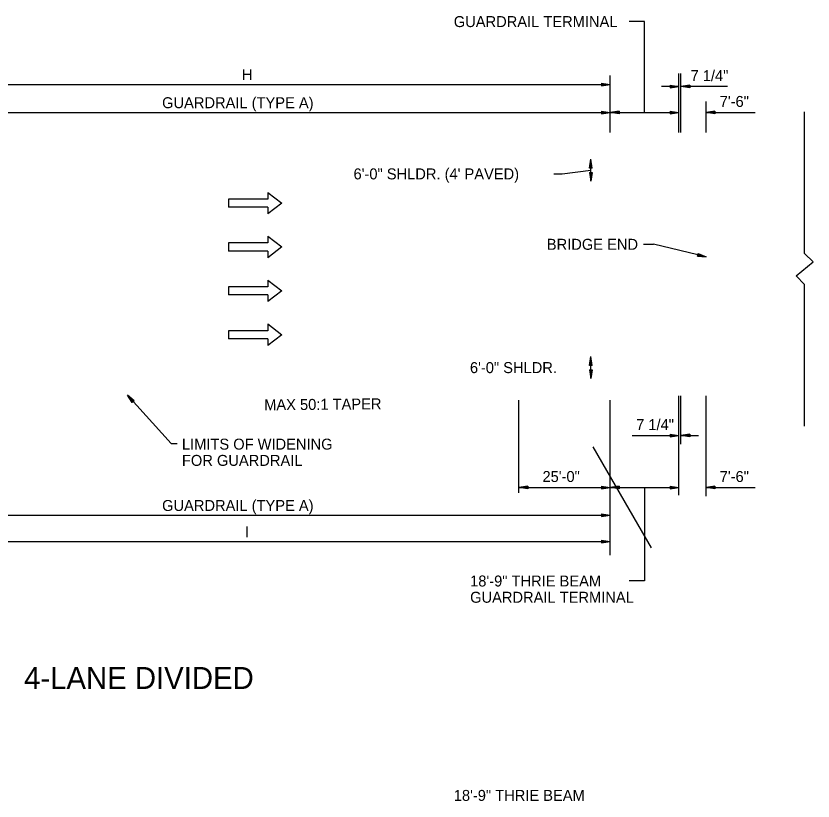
# Model space of a CAD drawing. Extents: x 1373853 to 1374003, y 380191 to 380927.
# Drawn here: x 1373883.7 to 1373927.34, y 380237.36 to 380280.32 of the extents above; entities that cross this region are included whole.
import ezdxf

# ---------------------------------------------------------------- set-up
doc = ezdxf.new("R2010")
doc.units = 0
for name, color, linetype in [('2', 7, 'Continuous'), ('7', 7, 'Continuous'), ('8', 7, 'Continuous'), ('Default', 7, 'Continuous'), ('E_Existing ROW', 7, 'Continuous'), ('R_Guardrail_Widening', 7, 'Continuous')]:
    doc.layers.add(name, color=color, linetype=linetype)

msp = doc.modelspace()

# ---------------------------------------------------------------- linework, layer by layer
at = {"layer": '2'}
for p, q in [((1373916.236, 380273.948), (1373916.236, 380277.055)), ((1373919.986, 380273.948), (1373919.986, 380277.175)), ((1373920.107, 380273.948), (1373920.107, 380277.175)), ((1373876.236, 380276.575), (1373916.236, 380276.575)), ((1373919.986, 380276.454), (1373919.045, 380276.454)), ((1373922.65, 380276.454), (1373920.107, 380276.454)), ((1373921.486, 380273.948), (1373921.486, 380275.64)), ((1373876.236, 380275.04), (1373916.236, 380275.04)), ((1373916.236, 380275.04), (1373919.986, 380275.04)), ((1373921.486, 380275.04), (1373924.16, 380275.04)), ((1373915.169, 380271.276), (1373915.166, 380272.476)), ((1373918.056, 380267.823), (1373918.603, 380267.823)), ((1373921.486, 380267.134), (1373918.603, 380267.823)), ((1373915.169, 380260.476), (1373915.166, 380261.676)), ((1373889.802, 380259.571), (1373892.201, 380256.921)), ((1373919.986, 380254.098), (1373919.986, 380259.537)), ((1373920.107, 380256.892), (1373920.107, 380259.537)), ((1373921.486, 380254.037), (1373921.486, 380259.537)), ((1373911.236, 380254.227), (1373911.236, 380259.294)), ((1373916.236, 380250.809), (1373916.236, 380259.294)), ((1373917.442, 380257.357), (1373919.986, 380257.357)), ((1373920.107, 380257.357), (1373921.067, 380257.359)), ((1373892.201, 380256.921), (1373892.52, 380256.921)), ((1373911.236, 380254.516), (1373916.236, 380254.516)), ((1373916.236, 380254.516), (1373919.986, 380254.516)), ((1373921.486, 380254.516), (1373924.16, 380254.516)), ((1373876.236, 380253), (1373916.236, 380253)), ((1373876.236, 380251.556), (1373916.236, 380251.556))]:
    msp.add_line(p, q, dxfattribs=at)
for points in [[(1373918.111, 380275.04), (1373918.111, 380280.01), (1373917.276, 380280.01)], [(1373913.145, 380271.676), (1373913.593, 380271.676), (1373915.167, 380271.876)], [(1373918.111, 380254.516), (1373918.111, 380249.399), (1373917.276, 380249.399)]]:
    msp.add_lwpolyline(points, dxfattribs=at)
at = {"layer": '7'}
for p, q in [((1373915.756, 380276.649), (1373916.236, 380276.575)), ((1373915.756, 380276.649), (1373915.756, 380276.503)), ((1373915.756, 380276.635), (1373916.155, 380276.575)), ((1373915.756, 380276.623), (1373916.073, 380276.575)), ((1373915.756, 380276.611), (1373915.992, 380276.575)), ((1373915.756, 380276.599), (1373915.913, 380276.575)), ((1373915.756, 380276.587), (1373915.832, 380276.575)), ((1373915.756, 380276.503), (1373916.236, 380276.575)), ((1373915.756, 380276.554), (1373915.913, 380276.575)), ((1373915.756, 380276.53), (1373916.073, 380276.575)), ((1373915.756, 380276.515), (1373916.155, 380276.575)), ((1373915.756, 380276.539), (1373915.992, 380276.575)), ((1373915.756, 380276.566), (1373915.832, 380276.575)), ((1373919.506, 380276.528), (1373919.986, 380276.454)), ((1373919.506, 380276.528), (1373919.506, 380276.383)), ((1373919.506, 380276.514), (1373919.905, 380276.454)), ((1373919.506, 380276.502), (1373919.823, 380276.454)), ((1373919.506, 380276.49), (1373919.742, 380276.454)), ((1373919.506, 380276.478), (1373919.663, 380276.454)), ((1373919.506, 380276.466), (1373919.582, 380276.454)), ((1373919.506, 380276.383), (1373919.986, 380276.454)), ((1373919.506, 380276.433), (1373919.663, 380276.454)), ((1373919.506, 380276.409), (1373919.823, 380276.454)), ((1373919.506, 380276.395), (1373919.905, 380276.454)), ((1373919.506, 380276.418), (1373919.742, 380276.454)), ((1373919.506, 380276.445), (1373919.582, 380276.454)), ((1373920.587, 380276.528), (1373920.107, 380276.454)), ((1373920.587, 380276.383), (1373920.107, 380276.454)), ((1373920.587, 380276.514), (1373920.188, 380276.454)), ((1373920.587, 380276.395), (1373920.188, 380276.454)), ((1373920.587, 380276.502), (1373920.269, 380276.454)), ((1373920.587, 380276.409), (1373920.269, 380276.454)), ((1373920.587, 380276.49), (1373920.35, 380276.454)), ((1373920.587, 380276.418), (1373920.35, 380276.454)), ((1373920.587, 380276.478), (1373920.429, 380276.454)), ((1373920.587, 380276.433), (1373920.429, 380276.454)), ((1373920.587, 380276.466), (1373920.51, 380276.454)), ((1373920.587, 380276.445), (1373920.51, 380276.454)), ((1373920.587, 380276.528), (1373920.587, 380276.383)), ((1373915.756, 380275.114), (1373916.236, 380275.04)), ((1373915.756, 380275.114), (1373915.756, 380274.968)), ((1373915.756, 380275.1), (1373916.155, 380275.04)), ((1373915.756, 380275.088), (1373916.073, 380275.04)), ((1373915.756, 380275.076), (1373915.992, 380275.04)), ((1373916.716, 380275.114), (1373916.236, 380275.04)), ((1373916.716, 380275.1), (1373916.317, 380275.04)), ((1373916.716, 380275.088), (1373916.398, 380275.04)), ((1373916.716, 380275.076), (1373916.479, 380275.04)), ((1373916.716, 380275.114), (1373916.716, 380274.968)), ((1373919.506, 380275.114), (1373919.986, 380275.04)), ((1373919.506, 380275.114), (1373919.506, 380274.968)), ((1373919.506, 380275.1), (1373919.905, 380275.04)), ((1373919.506, 380275.088), (1373919.823, 380275.04)), ((1373919.506, 380275.076), (1373919.742, 380275.04)), ((1373921.966, 380275.114), (1373921.486, 380275.04)), ((1373921.966, 380275.1), (1373921.567, 380275.04)), ((1373921.966, 380275.088), (1373921.648, 380275.04)), ((1373921.966, 380275.076), (1373921.729, 380275.04)), ((1373921.966, 380275.114), (1373921.966, 380274.968)), ((1373915.756, 380275.064), (1373915.913, 380275.04)), ((1373915.756, 380275.052), (1373915.832, 380275.04)), ((1373915.756, 380274.968), (1373916.236, 380275.04)), ((1373915.756, 380275.019), (1373915.913, 380275.04)), ((1373915.756, 380274.995), (1373916.073, 380275.04)), ((1373915.756, 380274.98), (1373916.155, 380275.04)), ((1373915.756, 380275.004), (1373915.992, 380275.04)), ((1373915.756, 380275.031), (1373915.832, 380275.04)), ((1373916.716, 380274.968), (1373916.236, 380275.04)), ((1373916.716, 380274.98), (1373916.317, 380275.04)), ((1373916.716, 380274.995), (1373916.398, 380275.04)), ((1373916.716, 380275.004), (1373916.479, 380275.04)), ((1373916.716, 380275.064), (1373916.558, 380275.04)), ((1373916.716, 380275.019), (1373916.558, 380275.04)), ((1373916.716, 380275.052), (1373916.639, 380275.04)), ((1373916.716, 380275.031), (1373916.639, 380275.04)), ((1373919.506, 380275.064), (1373919.663, 380275.04)), ((1373919.506, 380275.052), (1373919.582, 380275.04)), ((1373919.506, 380274.968), (1373919.986, 380275.04)), ((1373919.506, 380275.019), (1373919.663, 380275.04)), ((1373919.506, 380274.995), (1373919.823, 380275.04)), ((1373919.506, 380274.98), (1373919.905, 380275.04)), ((1373919.506, 380275.004), (1373919.742, 380275.04)), ((1373919.506, 380275.031), (1373919.582, 380275.04)), ((1373921.966, 380274.968), (1373921.486, 380275.04)), ((1373921.966, 380274.98), (1373921.567, 380275.04)), ((1373921.966, 380274.995), (1373921.648, 380275.04)), ((1373921.966, 380275.004), (1373921.729, 380275.04)), ((1373921.966, 380275.064), (1373921.808, 380275.04)), ((1373921.966, 380275.019), (1373921.808, 380275.04)), ((1373921.966, 380275.052), (1373921.889, 380275.04)), ((1373921.966, 380275.031), (1373921.889, 380275.04)), ((1373915.094, 380271.996), (1373915.166, 380272.476)), ((1373915.237, 380271.996), (1373915.166, 380272.476)), ((1373915.106, 380271.996), (1373915.166, 380272.394)), ((1373915.118, 380271.996), (1373915.166, 380272.313)), ((1373915.13, 380271.996), (1373915.166, 380272.232)), ((1373915.142, 380271.996), (1373915.166, 380272.151)), ((1373915.154, 380271.996), (1373915.166, 380272.072)), ((1373915.226, 380271.996), (1373915.166, 380272.394)), ((1373915.214, 380271.996), (1373915.166, 380272.313)), ((1373915.202, 380271.996), (1373915.166, 380272.232)), ((1373915.19, 380271.996), (1373915.166, 380272.151)), ((1373915.178, 380271.996), (1373915.166, 380272.072)), ((1373915.237, 380271.996), (1373915.094, 380271.996)), ((1373915.095, 380271.756), (1373915.169, 380271.276)), ((1373915.095, 380271.756), (1373915.24, 380271.756)), ((1373915.109, 380271.756), (1373915.169, 380271.357)), ((1373915.121, 380271.756), (1373915.169, 380271.438)), ((1373915.133, 380271.756), (1373915.169, 380271.519)), ((1373915.145, 380271.756), (1373915.169, 380271.598)), ((1373915.157, 380271.756), (1373915.169, 380271.679)), ((1373915.24, 380271.756), (1373915.169, 380271.276)), ((1373915.19, 380271.756), (1373915.169, 380271.598)), ((1373915.214, 380271.756), (1373915.169, 380271.438)), ((1373915.228, 380271.756), (1373915.169, 380271.357)), ((1373915.205, 380271.756), (1373915.169, 380271.519)), ((1373915.178, 380271.756), (1373915.169, 380271.679)), ((1373921.005, 380267.176), (1373921.038, 380267.315)), ((1373921.016, 380267.222), (1373921.172, 380267.209)), ((1373921.018, 380267.234), (1373921.093, 380267.228)), ((1373921.023, 380267.255), (1373921.093, 380267.228)), ((1373921.027, 380267.269), (1373921.172, 380267.209)), ((1373921.03, 380267.28), (1373921.249, 380267.191)), ((1373921.032, 380267.292), (1373921.328, 380267.172)), ((1373921.035, 380267.303), (1373921.409, 380267.153)), ((1373921.038, 380267.315), (1373921.486, 380267.134)), ((1373921.005, 380267.176), (1373921.486, 380267.134)), ((1373921.007, 380267.187), (1373921.409, 380267.153)), ((1373921.01, 380267.199), (1373921.328, 380267.172)), ((1373921.013, 380267.211), (1373921.249, 380267.191)), ((1373915.094, 380261.196), (1373915.166, 380261.676)), ((1373915.106, 380261.196), (1373915.166, 380261.594)), ((1373915.237, 380261.196), (1373915.166, 380261.676)), ((1373915.226, 380261.196), (1373915.166, 380261.594)), ((1373915.237, 380261.196), (1373915.094, 380261.196)), ((1373915.118, 380261.196), (1373915.166, 380261.513)), ((1373915.13, 380261.196), (1373915.166, 380261.432)), ((1373915.142, 380261.196), (1373915.166, 380261.351)), ((1373915.154, 380261.196), (1373915.166, 380261.272)), ((1373915.214, 380261.196), (1373915.166, 380261.513)), ((1373915.202, 380261.196), (1373915.166, 380261.432)), ((1373915.19, 380261.196), (1373915.166, 380261.351)), ((1373915.178, 380261.196), (1373915.166, 380261.272)), ((1373915.095, 380260.956), (1373915.169, 380260.476)), ((1373915.095, 380260.956), (1373915.24, 380260.956)), ((1373915.109, 380260.956), (1373915.169, 380260.557)), ((1373915.121, 380260.956), (1373915.169, 380260.638)), ((1373915.133, 380260.956), (1373915.169, 380260.719)), ((1373915.145, 380260.956), (1373915.169, 380260.798)), ((1373915.157, 380260.956), (1373915.169, 380260.879)), ((1373915.24, 380260.956), (1373915.169, 380260.476)), ((1373915.19, 380260.956), (1373915.169, 380260.798)), ((1373915.214, 380260.956), (1373915.169, 380260.638)), ((1373915.228, 380260.956), (1373915.169, 380260.557)), ((1373915.205, 380260.956), (1373915.169, 380260.719)), ((1373915.178, 380260.956), (1373915.169, 380260.879)), ((1373890.177, 380259.263), (1373889.802, 380259.571)), ((1373890.07, 380259.169), (1373889.802, 380259.571)), ((1373890.169, 380259.256), (1373889.857, 380259.513)), ((1373890.081, 380259.174), (1373889.857, 380259.513)), ((1373890.092, 380259.185), (1373889.913, 380259.45)), ((1373890.158, 380259.248), (1373889.913, 380259.45)), ((1373890.15, 380259.24), (1373889.965, 380259.392)), ((1373890.098, 380259.194), (1373889.965, 380259.392)), ((1373890.106, 380259.2), (1373890.018, 380259.332)), ((1373890.139, 380259.232), (1373890.018, 380259.332)), ((1373890.177, 380259.263), (1373890.07, 380259.169)), ((1373890.114, 380259.208), (1373890.074, 380259.272)), ((1373890.133, 380259.22), (1373890.074, 380259.272)), ((1373919.506, 380257.431), (1373919.986, 380257.357)), ((1373919.506, 380257.431), (1373919.506, 380257.285)), ((1373919.506, 380257.417), (1373919.905, 380257.357)), ((1373919.506, 380257.405), (1373919.823, 380257.357)), ((1373919.506, 380257.393), (1373919.742, 380257.357)), ((1373919.506, 380257.381), (1373919.663, 380257.357)), ((1373919.506, 380257.369), (1373919.582, 380257.357)), ((1373919.506, 380257.285), (1373919.986, 380257.357)), ((1373919.506, 380257.335), (1373919.663, 380257.357)), ((1373919.506, 380257.311), (1373919.823, 380257.357)), ((1373919.506, 380257.297), (1373919.905, 380257.357)), ((1373919.506, 380257.321), (1373919.742, 380257.357)), ((1373919.506, 380257.347), (1373919.582, 380257.357)), ((1373920.587, 380257.431), (1373920.107, 380257.357)), ((1373920.587, 380257.285), (1373920.107, 380257.357)), ((1373920.587, 380257.417), (1373920.188, 380257.357)), ((1373920.587, 380257.297), (1373920.188, 380257.357)), ((1373920.587, 380257.405), (1373920.269, 380257.357)), ((1373920.587, 380257.311), (1373920.269, 380257.357)), ((1373920.587, 380257.393), (1373920.35, 380257.357)), ((1373920.587, 380257.321), (1373920.35, 380257.357)), ((1373920.587, 380257.381), (1373920.429, 380257.357)), ((1373920.587, 380257.335), (1373920.429, 380257.357)), ((1373920.587, 380257.369), (1373920.51, 380257.357)), ((1373920.587, 380257.347), (1373920.51, 380257.357)), ((1373920.587, 380257.431), (1373920.587, 380257.285)), ((1373911.716, 380254.59), (1373911.236, 380254.516)), ((1373911.716, 380254.576), (1373911.317, 380254.516)), ((1373911.716, 380254.564), (1373911.398, 380254.516)), ((1373911.716, 380254.59), (1373911.716, 380254.444)), ((1373915.756, 380254.59), (1373916.236, 380254.516)), ((1373915.756, 380254.59), (1373915.756, 380254.444)), ((1373915.756, 380254.576), (1373916.155, 380254.516)), ((1373915.756, 380254.564), (1373916.073, 380254.516)), ((1373916.716, 380254.59), (1373916.236, 380254.516)), ((1373916.716, 380254.576), (1373916.317, 380254.516)), ((1373916.716, 380254.564), (1373916.398, 380254.516)), ((1373916.716, 380254.59), (1373916.716, 380254.444)), ((1373919.506, 380254.59), (1373919.986, 380254.516)), ((1373919.506, 380254.59), (1373919.506, 380254.444)), ((1373919.506, 380254.576), (1373919.905, 380254.516)), ((1373919.506, 380254.564), (1373919.823, 380254.516)), ((1373921.966, 380254.59), (1373921.486, 380254.516)), ((1373921.966, 380254.576), (1373921.567, 380254.516)), ((1373921.966, 380254.564), (1373921.648, 380254.516)), ((1373921.966, 380254.59), (1373921.966, 380254.444)), ((1373911.716, 380254.444), (1373911.236, 380254.516)), ((1373911.716, 380254.456), (1373911.317, 380254.516)), ((1373911.716, 380254.471), (1373911.398, 380254.516)), ((1373911.716, 380254.552), (1373911.479, 380254.516)), ((1373911.716, 380254.48), (1373911.479, 380254.516)), ((1373911.716, 380254.54), (1373911.558, 380254.516)), ((1373911.716, 380254.494), (1373911.558, 380254.516)), ((1373911.716, 380254.528), (1373911.639, 380254.516)), ((1373911.716, 380254.506), (1373911.639, 380254.516)), ((1373915.756, 380254.552), (1373915.992, 380254.516)), ((1373915.756, 380254.54), (1373915.913, 380254.516)), ((1373915.756, 380254.528), (1373915.832, 380254.516)), ((1373915.756, 380254.444), (1373916.236, 380254.516)), ((1373915.756, 380254.494), (1373915.913, 380254.516)), ((1373915.756, 380254.471), (1373916.073, 380254.516)), ((1373915.756, 380254.456), (1373916.155, 380254.516)), ((1373915.756, 380254.48), (1373915.992, 380254.516)), ((1373915.756, 380254.506), (1373915.832, 380254.516)), ((1373916.716, 380254.444), (1373916.236, 380254.516)), ((1373916.716, 380254.456), (1373916.317, 380254.516)), ((1373916.716, 380254.471), (1373916.398, 380254.516)), ((1373916.716, 380254.552), (1373916.479, 380254.516)), ((1373916.716, 380254.48), (1373916.479, 380254.516)), ((1373916.716, 380254.54), (1373916.558, 380254.516)), ((1373916.716, 380254.494), (1373916.558, 380254.516)), ((1373916.716, 380254.528), (1373916.639, 380254.516)), ((1373916.716, 380254.506), (1373916.639, 380254.516)), ((1373919.506, 380254.552), (1373919.742, 380254.516)), ((1373919.506, 380254.54), (1373919.663, 380254.516)), ((1373919.506, 380254.528), (1373919.582, 380254.516)), ((1373919.506, 380254.444), (1373919.986, 380254.516)), ((1373919.506, 380254.494), (1373919.663, 380254.516)), ((1373919.506, 380254.471), (1373919.823, 380254.516)), ((1373919.506, 380254.456), (1373919.905, 380254.516)), ((1373919.506, 380254.48), (1373919.742, 380254.516)), ((1373919.506, 380254.506), (1373919.582, 380254.516)), ((1373921.966, 380254.444), (1373921.486, 380254.516)), ((1373921.966, 380254.456), (1373921.567, 380254.516)), ((1373921.966, 380254.471), (1373921.648, 380254.516)), ((1373921.966, 380254.552), (1373921.729, 380254.516)), ((1373921.966, 380254.48), (1373921.729, 380254.516)), ((1373921.966, 380254.54), (1373921.808, 380254.516)), ((1373921.966, 380254.494), (1373921.808, 380254.516)), ((1373921.966, 380254.528), (1373921.889, 380254.516)), ((1373921.966, 380254.506), (1373921.889, 380254.516)), ((1373915.756, 380253.074), (1373916.236, 380253)), ((1373915.756, 380253.074), (1373915.756, 380252.928)), ((1373915.756, 380253.06), (1373916.155, 380253)), ((1373915.756, 380253.048), (1373916.073, 380253)), ((1373915.756, 380253.036), (1373915.992, 380253)), ((1373915.756, 380253.024), (1373915.913, 380253)), ((1373915.756, 380253.012), (1373915.832, 380253)), ((1373915.756, 380252.928), (1373916.236, 380253)), ((1373915.756, 380252.979), (1373915.913, 380253)), ((1373915.756, 380252.955), (1373916.073, 380253)), ((1373915.756, 380252.94), (1373916.155, 380253)), ((1373915.756, 380252.964), (1373915.992, 380253)), ((1373915.756, 380252.991), (1373915.832, 380253)), ((1373915.756, 380251.63), (1373916.236, 380251.556)), ((1373915.756, 380251.63), (1373915.756, 380251.484)), ((1373915.756, 380251.615), (1373916.155, 380251.556)), ((1373915.756, 380251.603), (1373916.073, 380251.556)), ((1373915.756, 380251.591), (1373915.992, 380251.556)), ((1373915.756, 380251.579), (1373915.913, 380251.556)), ((1373915.756, 380251.567), (1373915.832, 380251.556)), ((1373915.756, 380251.484), (1373916.236, 380251.556)), ((1373915.756, 380251.534), (1373915.913, 380251.556)), ((1373915.756, 380251.51), (1373916.073, 380251.556)), ((1373915.756, 380251.496), (1373916.155, 380251.556)), ((1373915.756, 380251.52), (1373915.992, 380251.556)), ((1373915.756, 380251.546), (1373915.832, 380251.556))]:
    msp.add_line(p, q, dxfattribs=at)
at = {"layer": 'Default'}
for p, q in [((1373897.492, 380270.296), (1373895.331, 380270.296)), ((1373895.331, 380270.296), (1373895.331, 380269.855)), ((1373897.492, 380270.663), (1373897.492, 380270.296)), ((1373897.492, 380270.663), (1373898.255, 380270.076)), ((1373897.492, 380269.855), (1373895.331, 380269.855)), ((1373898.255, 380270.076), (1373897.492, 380269.488)), ((1373897.492, 380269.855), (1373897.492, 380269.488)), ((1373897.492, 380268.263), (1373897.492, 380267.896)), ((1373897.492, 380268.263), (1373898.255, 380267.676)), ((1373897.492, 380267.896), (1373895.331, 380267.896)), ((1373895.331, 380267.896), (1373895.331, 380267.455)), ((1373898.255, 380267.676), (1373897.492, 380267.088)), ((1373897.492, 380267.455), (1373895.331, 380267.455)), ((1373897.492, 380267.455), (1373897.492, 380267.088)), ((1373897.492, 380265.496), (1373895.331, 380265.496)), ((1373895.331, 380265.496), (1373895.331, 380265.055)), ((1373897.492, 380265.863), (1373897.492, 380265.496)), ((1373897.492, 380265.863), (1373898.255, 380265.276)), ((1373897.492, 380265.055), (1373895.331, 380265.055)), ((1373898.255, 380265.276), (1373897.492, 380264.688)), ((1373897.492, 380265.055), (1373897.492, 380264.688)), ((1373897.492, 380263.463), (1373897.492, 380263.096)), ((1373897.492, 380263.463), (1373898.255, 380262.876)), ((1373897.492, 380263.096), (1373895.331, 380263.096)), ((1373895.331, 380263.096), (1373895.331, 380262.655)), ((1373898.255, 380262.876), (1373897.492, 380262.288)), ((1373897.492, 380262.655), (1373895.331, 380262.655)), ((1373897.492, 380262.655), (1373897.492, 380262.288))]:
    msp.add_line(p, q, dxfattribs=at)
at = {"layer": 'E_Existing ROW'}
msp.add_lwpolyline([(1373915.286, 380256.749), (1373918.482, 380251.213)], dxfattribs=at)
at = {"layer": 'R_Guardrail_Widening'}
for p, q in [((1373926.871, 380267.322), (1373926.871, 380275.076)), ((1373927.337, 380266.857), (1373926.871, 380267.322)), ((1373926.405, 380266.095), (1373927.337, 380266.857)), ((1373926.871, 380265.629), (1373926.405, 380266.095)), ((1373926.871, 380257.876), (1373926.871, 380265.629))]:
    msp.add_line(p, q, dxfattribs=at)

# ---------------------------------------------------------------- texts
at = {"layer": '2'}
for s, rotation, p in [('GUARDRAIL TERMINAL', 360, (1373907.669, 380279.71)), ('H', 0, (1373896.066, 380276.806)), ('7 1/4"', 360, (1373920.632, 380276.754)), ('7\'-6"', 0, (1373922.227, 380275.34)), ('GUARDRAIL (TYPE A)', 0, (1373891.7, 380275.271)), ('MAX 50:1 TAPER', 0.5107, (1373897.291, 380258.738)), ('7 1/4"', 0, (1373917.651, 380257.657)), ('LIMITS OF WIDENING', 0, (1373892.787, 380256.588)), ('FOR GUARDRAIL', 0, (1373892.787, 380255.698)), ('25\'-0"', 0, (1373912.524, 380254.816)), ('7\'-6"', 0, (1373922.227, 380254.816)), ('GUARDRAIL (TYPE A)', 0, (1373891.7, 380253.231)), ('I', 0, (1373896.236, 380251.787)), ('18\'-9" THRIE BEAM', 0, (1373908.563, 380249.099)), ('GUARDRAIL TERMINAL', 0, (1373908.563, 380248.209)), ('18\'-9" THRIE BEAM', 360, (1373907.669, 380237.366))]:
    msp.add_text(s, height=0.6, rotation=rotation, dxfattribs=at).set_placement(p)
for s, p in [('6\'-0" SHLDR. (4\' PAVED)', (1373902.18, 380271.376)), ('BRIDGE END', (1373912.763, 380267.523)), ('6\'-0" SHLDR.', (1373908.553, 380260.776))]:
    msp.add_text(s, height=0.6, dxfattribs=at).set_placement(p)
at = {"layer": '8'}
msp.add_text('4-LANE DIVIDED', height=1.2, rotation=0, dxfattribs=at).set_placement((1373884.145, 380243.492))

doc.saveas('drawing.dxf')
